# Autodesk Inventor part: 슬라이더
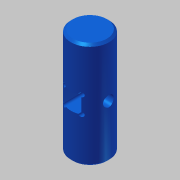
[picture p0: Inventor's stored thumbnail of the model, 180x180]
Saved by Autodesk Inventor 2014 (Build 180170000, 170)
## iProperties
Company: 한국ATC센터
Created: 2015-04
Part Number: 슬라이더
Document SubType Name: Modeling
Designer: KYOUNG IL JANG
Density: 7.85 g/cm^3
Material: 강
Mass: 88.0136 g
Surface Area: 38.892 cm^2
Volume: 11.2119 cm^3
Appearance: 청록색
Author: KYOUNG IL JANG
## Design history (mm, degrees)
sketch "스케치1"
  geometry: C1 r 9 at (0, 0); 1 further point
  constraints: 1 centre point, 1 coincident
  dimensions: "d0" = 18 diameter of C1
extrude "돌출1" new body sketch "스케치1" stored distance "d1" = 50; taper "d2" = 0 deg
node "작업 평면1"
sketch "스케치3"
  geometry: L1 (4, 25)-(-4, 25); L2 (-4, 25)-(-4, -25); L3 (-4, -25)-(4, -25); L4 (4, -25)-(4, 25); 3 further points
  constraints: 8 end point, 2 midpoint, 2 parallel, 1 horizontal, 1 horizontal alignment, 1 perpendicular, 1 vertical alignment
  dimensions: "d5" = 8 distance of L1.start L1.end; "d6" = 50 distance of L1.end L2.end
extrude "돌출3" cut sketch "스케치3" stored distance "d7" = 8; taper "d8" = 0 deg
sketch "스케치4"
  geometry: 5 further points
hole "구멍1" sketch "스케치4" at (4, 4), (-4, 4), (-4, -4), (4, -4) diameter "d9" = 2; stored, may be unused: countersink angle "d13" = 90 deg, drill point angle "d15" = 118 deg; dims "d10" = 6, "d11" = 4, "d12" = 2, "d14" = 8
node "작업 평면2"
sketch "스케치5"
  geometry: 1 further point
hole "구멍2" sketch "스케치5" at (0, 0) diameter "d16" = 5; stored, may be unused: countersink angle "d20" = 90 deg, drill point angle "d22" = 118 deg; dims "d17" = 6, "d18" = 4, "d19" = 2, "d21" = 8
chamfer "모따기1" distance "d23" = 1; stored, may be unused: second distance "d24" = 2, angle "d25" = 45 deg
node "솔리드1"
mirror "대칭1"
